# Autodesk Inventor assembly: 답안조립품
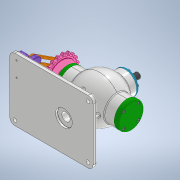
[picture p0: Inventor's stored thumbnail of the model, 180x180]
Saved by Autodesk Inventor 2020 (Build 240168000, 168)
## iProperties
Created: 2022-09
Part Number: 답안조립품
Document SubType Name: Assembly
Designer: 101-13
Mass: 3198.03 g
Surface Area: 2483.43 cm^2
Volume: 906.947 cm^3
Density: 3.52615 g/cm^3
Author: 101-13
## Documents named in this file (20)
- C:\Users\101-13\Desktop\620906V1001\답안조립품.iam
- C:\Users\101-13\Desktop\620906V1001\본체.ipt
- C:\Users\101-13\Desktop\620906V1001\본체커버.ipt
- C:\Users\101-13\Desktop\620906V1001\베어링 6202.ipt
- C:\Users\101-13\Desktop\620906V1001\앞커버.ipt
- C:\Users\101-13\Desktop\620906V1001\뒤커버.ipt
- C:\Users\101-13\Desktop\620906V1001\축.ipt
- C:\Users\101-13\Desktop\620906V1001\오일실.ipt
- C:\Users\101-13\Desktop\620906V1001\와셔 8x17.ipt
- C:\Users\101-13\Desktop\620906V1001\너트 M8x1.ipt
- C:\Users\101-13\Desktop\620906V1001\키 3x3.ipt
- C:\Users\101-13\Desktop\620906V1001\스프로킷.ipt
- C:\Users\101-13\Desktop\620906V1001\힌지.ipt
- C:\Users\101-13\Desktop\620906V1001\커넥트 암.ipt
- C:\Users\101-13\Desktop\620906V1001\칼라.ipt
- C:\Users\101-13\Desktop\620906V1001\연결 핀.ipt
- C:\Users\101-13\Desktop\620906V1001\슬라이드.ipt
- C:\Users\101-13\Desktop\620906V1001\슬라이드 커버.ipt
- C:\Users\101-13\Desktop\620906V1001\볼트 M4x12.ipt
- C:\Users\101-13\Desktop\620906V1001\가변스프링.ipt
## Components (1 placed, 1 different names)
1. 가변스프링:1
